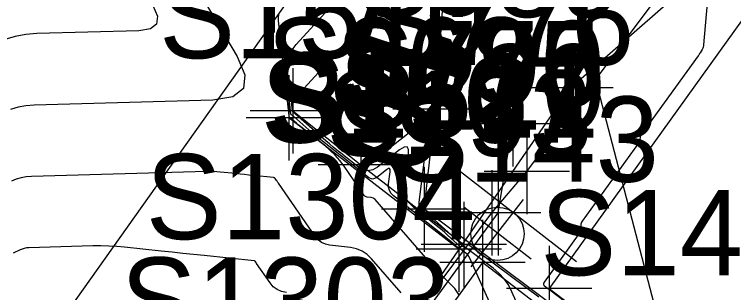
# Model space of a CAD drawing. Extents: x 816928 to 825690, y 436959 to 448212.
# Drawn here: x 818945.7 to 818979.44, y 445191.59 to 445204.64 of the extents above; entities that cross this region are included whole.
import ezdxf

# ---------------------------------------------------------------- set-up
doc = ezdxf.new("R2010")
doc.units = 0
for name, color, linetype in [('SURVEY - CONTOURS - Index with Text', 7, 'Continuous'), ('SURVEY - CONTOURS - Intermediate with optional Text', 7, 'Continuous'), ('SURVEY - DRAINAGE - Bridge Hydraulic Data - Points - Numbers', 7, 'Continuous'), ('SURVEY - DRAINAGE - Bridges', 7, 'Continuous'), ('SURVEY - DRAINAGE - Bridges - Points - Locators', 7, 'Continuous'), ('SURVEY - DRAINAGE - Bridges - Points - Numbers', 7, 'Continuous'), ('SURVEY - DRAINAGE - Bridges Text', 7, 'Continuous'), ('SURVEY - DRAINAGE - Natural Features - Points - Numbers', 7, 'Continuous'), ('SURVEY - DTM - Breaklines', 7, 'Continuous'), ('SURVEY - DTM - Breaklines - Points - Locators', 7, 'Continuous'), ('SURVEY - DTM - Breaklines - Points - Numbers', 7, 'Continuous'), ('SURVEY - PROPERTY - Parcels', 7, 'Continuous'), ('SURVEY - PROPERTY - ROW Lines', 7, 'Continuous'), ('SURVEY - ROADSIDE BARRIERS - Points - Locators', 7, 'Continuous'), ('SURVEY - ROADSIDE BARRIERS - Points - Numbers', 7, 'Continuous'), ('SURVEY - ROADSIDE BARRIERS with Text', 7, 'Continuous'), ('SURVEY - TRAFFIC CONTROL - Signs - Points - Locators', 7, 'Continuous'), ('SURVEY - TRAFFIC CONTROL - Signs - Points - Numbers', 7, 'Continuous'), ('SURVEY - TRAFFIC CONTROL - Signs and Devices with Text', 7, 'Continuous'), ('SURVEY - TRANSPORTATION - Roads', 7, 'Continuous'), ('SURVEY - TRANSPORTATION - Roads - Points - Locators', 7, 'Continuous'), ('SURVEY - TRANSPORTATION - Roads - Points - Numbers', 7, 'Continuous'), ('SURVEY - UTILITIES - Gas - Points - Locators', 7, 'Continuous'), ('SURVEY - UTILITIES - Gas - Points - Numbers', 7, 'Continuous'), ('SURVEY - UTILITIES - Gas with Text', 7, 'Continuous'), ('SURVEY - UTILITIES - Telephone (Underground) - Points - Locators', 7, 'Continuous'), ('SURVEY - UTILITIES - Telephone (Underground) - Points - Numbers', 7, 'Continuous'), ('SURVEY - UTILITIES - Telephone (Underground) with Text', 7, 'Continuous'), ('SURVEY - UTILITIES - Water - Points - Locators', 7, 'Continuous'), ('SURVEY - UTILITIES - Water with Text', 7, 'Continuous')]:
    doc.layers.add(name, color=color, linetype=linetype)

msp = doc.modelspace()

# ---------------------------------------------------------------- linework, layer by layer
at = {"layer": 'SURVEY - CONTOURS - Index with Text'}
for points in [[(818963.072, 445198.196), (818964.282, 445199.141), (818964.664, 445199.376), (818964.918, 445199.383), (818965.042, 445199.162), (818965.036, 445198.714), (818964.676, 445195.814), (818964.675, 445195.724), (818964.696, 445195.642), (818964.738, 445195.57), (818964.802, 445195.506), (818965.045, 445195.311), (818965.097, 445195.269), (818965.148, 445195.226), (818965.199, 445195.183), (818965.249, 445195.139), (818966.684, 445193.85), (818966.712, 445193.83), (818966.742, 445193.818), (818966.774, 445193.815), (818966.808, 445193.821), (818966.922, 445193.854), (818966.946, 445193.858), (818966.969, 445193.857), (818966.991, 445193.85), (818967.012, 445193.838), (818970.304, 445191.381)], [(818958.464, 445191.583), (818958.233, 445191.633), (818958.029, 445191.726), (818957.85, 445191.862), (818957.697, 445192.042), (818957.064, 445192.955), (818957.054, 445192.968), (818957.045, 445192.982), (818957.035, 445192.995), (818957.026, 445193.009), (818956.995, 445193.053), (818956.988, 445193.061), (818956.98, 445193.068), (818956.97, 445193.072), (818956.959, 445193.074), (818954.61, 445193.321), (818954.107, 445193.374), (818953.603, 445193.427), (818953.1, 445193.48), (818952.596, 445193.533), (818950.872, 445193.715), (818950.502, 445193.747), (818950.132, 445193.768), (818949.761, 445193.776), (818949.39, 445193.772), (818946.378, 445193.687), (818946.272, 445193.679), (818946.168, 445193.659), (818946.067, 445193.629), (818945.969, 445193.588), (818945.651, 445193.436)]]:
    msp.add_lwpolyline(points, dxfattribs=at)
at = {"layer": 'SURVEY - CONTOURS - Intermediate with optional Text'}
for points in [[(818953.421, 445207.295), (818956.152, 445202.668), (818956.52, 445201.796), (818956.454, 445201.165), (818955.954, 445200.773), (818955.02, 445200.62), (818946.626, 445200.384), (818946.248, 445200.354), (818945.88, 445200.286), (818945.521, 445200.178)], [(818978.2, 445205.161), (818978.033, 445203.213), (818978.025, 445203.155), (818978.011, 445203.1), (818977.991, 445203.046), (818977.964, 445202.995), (818977.867, 445202.83), (818977.846, 445202.795), (818977.824, 445202.761), (818977.801, 445202.727), (818977.777, 445202.693), (818975.116, 445199.013), (818975.093, 445198.976), (818975.074, 445198.938), (818975.06, 445198.897), (818975.05, 445198.855), (818975.027, 445198.713), (818975.02, 445198.683), (818975.01, 445198.655), (818974.997, 445198.628), (818974.981, 445198.602), (818972.338, 445194.942), (818972.308, 445194.894), (818972.287, 445194.843), (818972.274, 445194.789), (818972.27, 445194.733), (818972.271, 445194.544), (818972.268, 445194.505), (818972.259, 445194.467), (818972.244, 445194.431), (818972.224, 445194.398), (818970.551, 445192.077), (818970.542, 445192.062), (818970.535, 445192.046), (818970.531, 445192.03), (818970.529, 445192.013), (818970.527, 445191.955), (818970.528, 445191.943), (818970.532, 445191.933), (818970.538, 445191.924), (818970.546, 445191.916), (818970.724, 445191.784), (818970.762, 445191.756), (818970.8, 445191.727), (818970.838, 445191.699), (818970.875, 445191.67), (818974.306, 445189.058)], [(818952.2, 445205.053), (818952.413, 445204.549), (818952.375, 445204.183), (818952.086, 445203.956), (818951.545, 445203.868), (818946.75, 445203.733), (818946.237, 445203.692), (818945.736, 445203.599), (818945.249, 445203.453)], [(818968.975, 445188.929), (818967.068, 445193.202), (818967.033, 445193.269), (818966.991, 445193.33), (818966.94, 445193.385), (818966.883, 445193.433), (818966.603, 445193.642), (818966.599, 445193.644), (818966.596, 445193.645), (818966.592, 445193.646), (818966.588, 445193.645), (818966.575, 445193.641), (818966.572, 445193.641), (818966.569, 445193.641), (818966.567, 445193.642), (818966.564, 445193.643), (818966.438, 445193.757), (818966.41, 445193.781), (818966.383, 445193.805), (818966.355, 445193.829), (818966.326, 445193.852), (818963.488, 445196.123), (818963.371, 445196.241), (818963.293, 445196.375), (818963.256, 445196.524), (818963.257, 445196.69), (818963.328, 445197.258), (818963.329, 445197.355), (818963.302, 445197.403), (818963.247, 445197.402), (818963.165, 445197.351), (818962.702, 445196.99), (818962.603, 445196.932), (818962.504, 445196.912), (818962.405, 445196.932), (818962.307, 445196.99), (818960.158, 445198.683), (818959.994, 445198.814), (818959.832, 445198.948), (818959.671, 445199.083), (818959.513, 445199.22), (818958.807, 445199.84), (818958.792, 445199.853), (818958.776, 445199.866), (818958.761, 445199.879), (818958.745, 445199.891), (818958.694, 445199.932), (818958.684, 445199.942), (818958.677, 445199.952), (818958.671, 445199.964), (818958.669, 445199.978), (818958.463, 445201.834), (818958.458, 445202.219), (818958.532, 445202.579), (818958.685, 445202.912), (818958.916, 445203.22), (818960.445, 445204.886)], [(818969.864, 445189.783), (818969.042, 445191.626), (818968.874, 445191.946), (818968.671, 445192.238), (818968.431, 445192.5), (818968.155, 445192.734), (818966.816, 445193.733), (818966.8, 445193.743), (818966.782, 445193.749), (818966.764, 445193.75), (818966.745, 445193.746), (818966.681, 445193.728), (818966.668, 445193.726), (818966.655, 445193.727), (818966.643, 445193.731), (818966.632, 445193.739), (818966.026, 445194.284), (818965.895, 445194.399), (818965.763, 445194.513), (818965.629, 445194.625), (818965.494, 445194.735), (818964.402, 445195.609), (818964.202, 445195.81), (818964.069, 445196.039), (818964.004, 445196.295), (818964.007, 445196.579), (818964.189, 445198.043), (818964.192, 445198.293), (818964.123, 445198.416), (818963.982, 445198.412), (818963.769, 445198.281), (818962.732, 445197.472), (818962.51, 445197.342), (818962.289, 445197.299), (818962.067, 445197.343), (818961.845, 445197.474), (818961.013, 445198.13), (818960.835, 445198.271), (818960.66, 445198.415), (818960.486, 445198.562), (818960.315, 445198.71), (818958.771, 445200.065), (818958.769, 445200.068), (818958.766, 445200.07), (818958.764, 445200.072), (818958.761, 445200.074), (818958.752, 445200.081), (818958.751, 445200.082), (818958.749, 445200.084), (818958.749, 445200.086), (818958.748, 445200.089), (818958.713, 445200.401), (818958.713, 445200.466), (818958.725, 445200.527), (818958.751, 445200.583), (818958.79, 445200.635), (818962.81, 445205.015)], [(818966.548, 445191.502), (818966.46, 445191.644), (818966.359, 445191.776), (818966.246, 445191.901), (818965.76, 445192.388), (818965.724, 445192.424), (818965.688, 445192.46), (818965.652, 445192.496), (818965.617, 445192.531), (818965.5, 445192.648), (818965.475, 445192.674), (818965.451, 445192.699), (818965.427, 445192.725), (818965.404, 445192.752), (818962.628, 445195.947), (818962.587, 445195.986), (818962.541, 445196.016), (818962.491, 445196.037), (818962.435, 445196.048), (818962.245, 445196.07), (818962.207, 445196.079), (818962.173, 445196.094), (818962.143, 445196.117), (818962.117, 445196.147), (818961.168, 445197.514), (818960.965, 445197.785), (818960.744, 445198.039), (818960.504, 445198.275), (818960.246, 445198.494), (818959.067, 445199.423), (818959.034, 445199.45), (818959.001, 445199.477), (818958.968, 445199.504), (818958.936, 445199.532), (818958.832, 445199.623), (818958.809, 445199.643), (818958.787, 445199.662), (818958.764, 445199.681), (818958.741, 445199.7), (818958.639, 445199.781), (818958.619, 445199.8), (818958.605, 445199.821), (818958.594, 445199.845), (818958.589, 445199.871), (818958.095, 445204.328), (818958.092, 445204.52), (818958.129, 445204.699)], [(818963.85, 445191.575), (818962.461, 445193.174), (818962.25, 445193.377), (818962.015, 445193.532), (818961.754, 445193.639), (818961.467, 445193.698), (818960.489, 445193.811), (818960.291, 445193.854), (818960.115, 445193.934), (818959.961, 445194.051), (818959.83, 445194.206), (818958.085, 445196.72), (818958.065, 445196.749), (818958.044, 445196.779), (818958.024, 445196.808), (818958.003, 445196.837), (818957.937, 445196.933), (818957.921, 445196.952), (818957.903, 445196.965), (818957.882, 445196.975), (818957.859, 445196.98), (818956.905, 445197.08), (818956.7, 445197.102), (818956.496, 445197.123), (818956.291, 445197.145), (818956.087, 445197.166), (818955.357, 445197.243), (818955.201, 445197.257), (818955.045, 445197.265), (818954.888, 445197.269), (818954.731, 445197.267), (818946.502, 445197.036), (818946.26, 445197.016), (818946.024, 445196.972), (818945.794, 445196.904), (818945.57, 445196.81)]]:
    msp.add_lwpolyline(points, dxfattribs=at)
at = {"layer": 'SURVEY - DRAINAGE - Bridges'}
msp.add_lwpolyline([(818986.517, 445178.492), (818967.667, 445193.001), (818951.105, 445170.09), (818969.913, 445155.738), (818985.717, 445177.407), (818986.517, 445178.492)], dxfattribs=at)
at = {"layer": 'SURVEY - DRAINAGE - Bridges - Points - Locators'}
for p, q in [((818967.667, 445195.001), (818967.667, 445191.001)), ((818969.667, 445193.001), (818965.667, 445193.001))]:
    msp.add_line(p, q, dxfattribs=at)
at = {"layer": 'SURVEY - DRAINAGE - Bridges Text'}
msp.add_lwpolyline([(818964.904, 445232.428), (818977.092, 445185.746)], dxfattribs=at)
at = {"layer": 'SURVEY - DTM - Breaklines'}
msp.add_line((818966.547, 445193.618), (818958.574, 445199.778), dxfattribs=at)
for points in [[(818964.92, 445195.492), (818965.449, 445200.19), (818965.951, 445207.228), (818985.491, 445228.351), (818993.217, 445232.84), (818999.097, 445239.365), (819007.192, 445250.479), (819027.405, 445276.904), (819055.511, 445319.799), (819082.413, 445356.886)], [(819000.173, 445161.106), (819006.975, 445167.84), (819018.264, 445177.632), (819043.995, 445180.693), (819053.369, 445187.411), (819051.623, 445192.47), (819020.493, 445189.559), (819028.708, 445200.874), (819043.012, 445204.7), (819059.276, 445211.531), (819057.576, 445217.227), (819034.75, 445209.945), (819032.825, 445213.106), (819039.837, 445227.267), (819039.43, 445231.039), (819035.269, 445232.369), (819015.594, 445198.899), (819002.121, 445188.285), (818991.056, 445175.935), (818964.92, 445195.492)]]:
    msp.add_lwpolyline(points, dxfattribs=at)
at = {"layer": 'SURVEY - DTM - Breaklines - Points - Locators'}
for p, q in [((818957.887, 445207.786), (818957.887, 445203.786)), ((818965.449, 445202.19), (818965.449, 445198.19)), ((818958.574, 445201.778), (818958.574, 445197.778)), ((818967.449, 445200.19), (818963.449, 445200.19)), ((818960.574, 445199.778), (818956.574, 445199.778)), ((818964.92, 445197.492), (818964.92, 445193.492)), ((818966.92, 445195.492), (818962.92, 445195.492)), ((818966.547, 445195.618), (818966.547, 445191.618)), ((818968.547, 445193.618), (818964.547, 445193.618))]:
    msp.add_line(p, q, dxfattribs=at)
at = {"layer": 'SURVEY - PROPERTY - Parcels'}
msp.add_line((818939.168, 445178.006), (819170.276, 445503.188), dxfattribs=at)
at = {"layer": 'SURVEY - PROPERTY - ROW Lines'}
msp.add_line((818939.168, 445178.006), (819182.874, 445520.914), dxfattribs=at)
at = {"layer": 'SURVEY - ROADSIDE BARRIERS - Points - Locators'}
for p, q in [((818958.764, 445202.111), (818958.764, 445198.111)), ((818960.764, 445200.111), (818956.764, 445200.111)), ((818961.95, 445199.578), (818961.95, 445195.578)), ((818963.95, 445197.578), (818959.95, 445197.578)), ((818966.785, 445195.846), (818966.785, 445191.846)), ((818968.785, 445193.846), (818964.785, 445193.846))]:
    msp.add_line(p, q, dxfattribs=at)
at = {"layer": 'SURVEY - ROADSIDE BARRIERS with Text'}
msp.add_lwpolyline([(818958.764, 445200.111), (818961.95, 445197.578), (818966.785, 445193.846)], dxfattribs=at)
at = {"layer": 'SURVEY - TRAFFIC CONTROL - Signs - Points - Locators'}
for p, q in [((818967.135, 445192.795), (818969.586, 445195.957)), ((818969.941, 445193.151), (818966.78, 445195.601))]:
    msp.add_line(p, q, dxfattribs=at)
at = {"layer": 'SURVEY - TRAFFIC CONTROL - Signs and Devices with Text'}
msp.add_line((818966.147, 445197.641), (818972.075, 445193.046), dxfattribs=at)
msp.add_circle((818968.362, 445194.343), 1.25, dxfattribs=at)
at = {"layer": 'SURVEY - TRANSPORTATION - Roads'}
msp.add_lwpolyline([(819372.417, 445760.729), (819347.536, 445716.465), (819327.358, 445684.931), (819320.732, 445674.576), (819313.086, 445663.907), (819291.72, 445634.092), (819261.573, 445595.794), (819230.52, 445556.026), (819202.59, 445519.473), (819200.025, 445516.115), (819183.78, 445493.817), (819171.491, 445476.948), (819142.501, 445435.003), (819121.554, 445405.003), (819114.313, 445394.631), (819108.813, 445386.861), (819085.629, 445354.103), (819056.538, 445311.65), (819028.029, 445272.038), (818998.985, 445231.035), (818970.783, 445191.785), (818984.089, 445181.723)], dxfattribs=at)
at = {"layer": 'SURVEY - TRANSPORTATION - Roads - Points - Locators'}
for p, q in [((818970.783, 445193.785), (818970.783, 445189.785)), ((818972.783, 445191.785), (818968.783, 445191.785))]:
    msp.add_line(p, q, dxfattribs=at)
at = {"layer": 'SURVEY - UTILITIES - Gas - Points - Locators'}
for p, q in [((818969.738, 445199.267), (818969.738, 445195.267)), ((818968.105, 445197.328), (818968.105, 445193.328)), ((818971.738, 445197.267), (818967.738, 445197.267)), ((818970.105, 445195.328), (818966.105, 445195.328))]:
    msp.add_line(p, q, dxfattribs=at)
at = {"layer": 'SURVEY - UTILITIES - Gas with Text'}
for points in [[(818968.105, 445195.328), (818969.738, 445197.267), (819012.001, 445253.658), (819064.107, 445326.037), (819122.078, 445408.8), (819183.152, 445497.068), (819237.635, 445568.809), (819293.129, 445639.42), (819349.073, 445723.122), (819383.091, 445785.202)], [(818946.069, 445164.692), (818947.807, 445168.098), (818968.105, 445195.328)]]:
    msp.add_lwpolyline(points, dxfattribs=at)
at = {"layer": 'SURVEY - UTILITIES - Telephone (Underground) - Points - Locators'}
for p, q in [((818969.083, 445201.507), (818969.083, 445197.507)), ((818971.083, 445199.507), (818967.083, 445199.507)), ((818968.39, 445197.328), (818968.39, 445193.328)), ((818970.39, 445195.328), (818966.39, 445195.328))]:
    msp.add_line(p, q, dxfattribs=at)
at = {"layer": 'SURVEY - UTILITIES - Telephone (Underground) with Text'}
msp.add_lwpolyline([(818930.857, 445150.66), (818932.992, 445149.937), (818944.966, 445166.651), (818949.519, 445169.463), (818968.39, 445195.328), (818969.083, 445199.507), (818972.238, 445210.883), (818980.303, 445223.767), (818989.561, 445238.187), (819000.76, 445253.257)], dxfattribs=at)
at = {"layer": 'SURVEY - UTILITIES - Water - Points - Locators'}
for p, q in [((818971.795, 445203.192), (818971.795, 445199.192)), ((818973.795, 445201.192), (818969.795, 445201.192))]:
    msp.add_line(p, q, dxfattribs=at)
at = {"layer": 'SURVEY - UTILITIES - Water with Text'}
msp.add_lwpolyline([(818803.235, 444799.745), (818822.09, 444847.157), (818840.807, 444894.989), (818859.419, 444943.113), (818878.417, 444989.731), (818897.247, 445035.659), (818918.394, 445078.737), (818943.016, 445121.017), (818943.424, 445156.253), (818947.564, 445166.115), (818971.795, 445201.192), (819041.117, 445261.897), (819085.564, 445324.056), (819114.437, 445364.745), (819142.589, 445406.123), (819261.281, 445567.542), (819325.961, 445650.567), (819357.336, 445697.813), (819381.766, 445739.87), (819404.905, 445782.998)], dxfattribs=at)

# ---------------------------------------------------------------- texts
at = {"layer": 'SURVEY - CONTOURS - Index with Text'}
msp.add_text('310', height=5, rotation=251.7422, dxfattribs=at).set_placement((818963.576, 445208.918))
at = {"layer": 'SURVEY - DRAINAGE - Bridge Hydraulic Data - Points - Numbers'}
msp.add_text('S1304', height=4, dxfattribs=at).set_placement((818951.862, 445194.092))
at = {"layer": 'SURVEY - DRAINAGE - Bridges - Points - Numbers'}
msp.add_text('S193', height=4, dxfattribs=at).set_placement((818960.331, 445198.001))
at = {"layer": 'SURVEY - DRAINAGE - Natural Features - Points - Numbers'}
msp.add_text('S1303', height=4, dxfattribs=at).set_placement((818950.681, 445189.233))
at = {"layer": 'SURVEY - DTM - Breaklines - Points - Numbers'}
for s, p in [('S968', (818957.537, 445200.492)), ('S1507', (818957.259, 445198.618)), ('S145', (818970.37, 445192.397))]:
    msp.add_text(s, height=4, dxfattribs=at).set_placement(p)
at = {"layer": 'SURVEY - ROADSIDE BARRIERS - Points - Numbers'}
for s, p in [('S1510', (818952.489, 445202.578)), ('S1511', (818957.655, 445198.846))]:
    msp.add_text(s, height=4, dxfattribs=at).set_placement(p)
at = {"layer": 'SURVEY - TRAFFIC CONTROL - Signs - Points - Numbers'}
msp.add_text('S220', height=4, dxfattribs=at).set_placement((818960.921, 445199.234))
at = {"layer": 'SURVEY - TRANSPORTATION - Roads - Points - Numbers'}
msp.add_text('S143', height=4, dxfattribs=at).set_placement((818963.447, 445196.785))
at = {"layer": 'SURVEY - UTILITIES - Gas - Points - Numbers'}
for s, p in [('S776', (818962.292, 445202.267)), ('S775', (818960.769, 445200.328))]:
    msp.add_text(s, height=4, dxfattribs=at).set_placement(p)
at = {"layer": 'SURVEY - UTILITIES - Telephone (Underground) - Points - Numbers'}
for s, p in [('S789', (818961.731, 445204.507)), ('S790', (818960.881, 445200.328))]:
    msp.add_text(s, height=4, dxfattribs=at).set_placement(p)

doc.saveas('drawing.dxf')
